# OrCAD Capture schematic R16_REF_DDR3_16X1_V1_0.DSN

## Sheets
1 05 DRAM DDR3 16bitx1: size A3; title: R16_REF_DDR3_16X1; rev: 0.1; note: DDR3 16X1
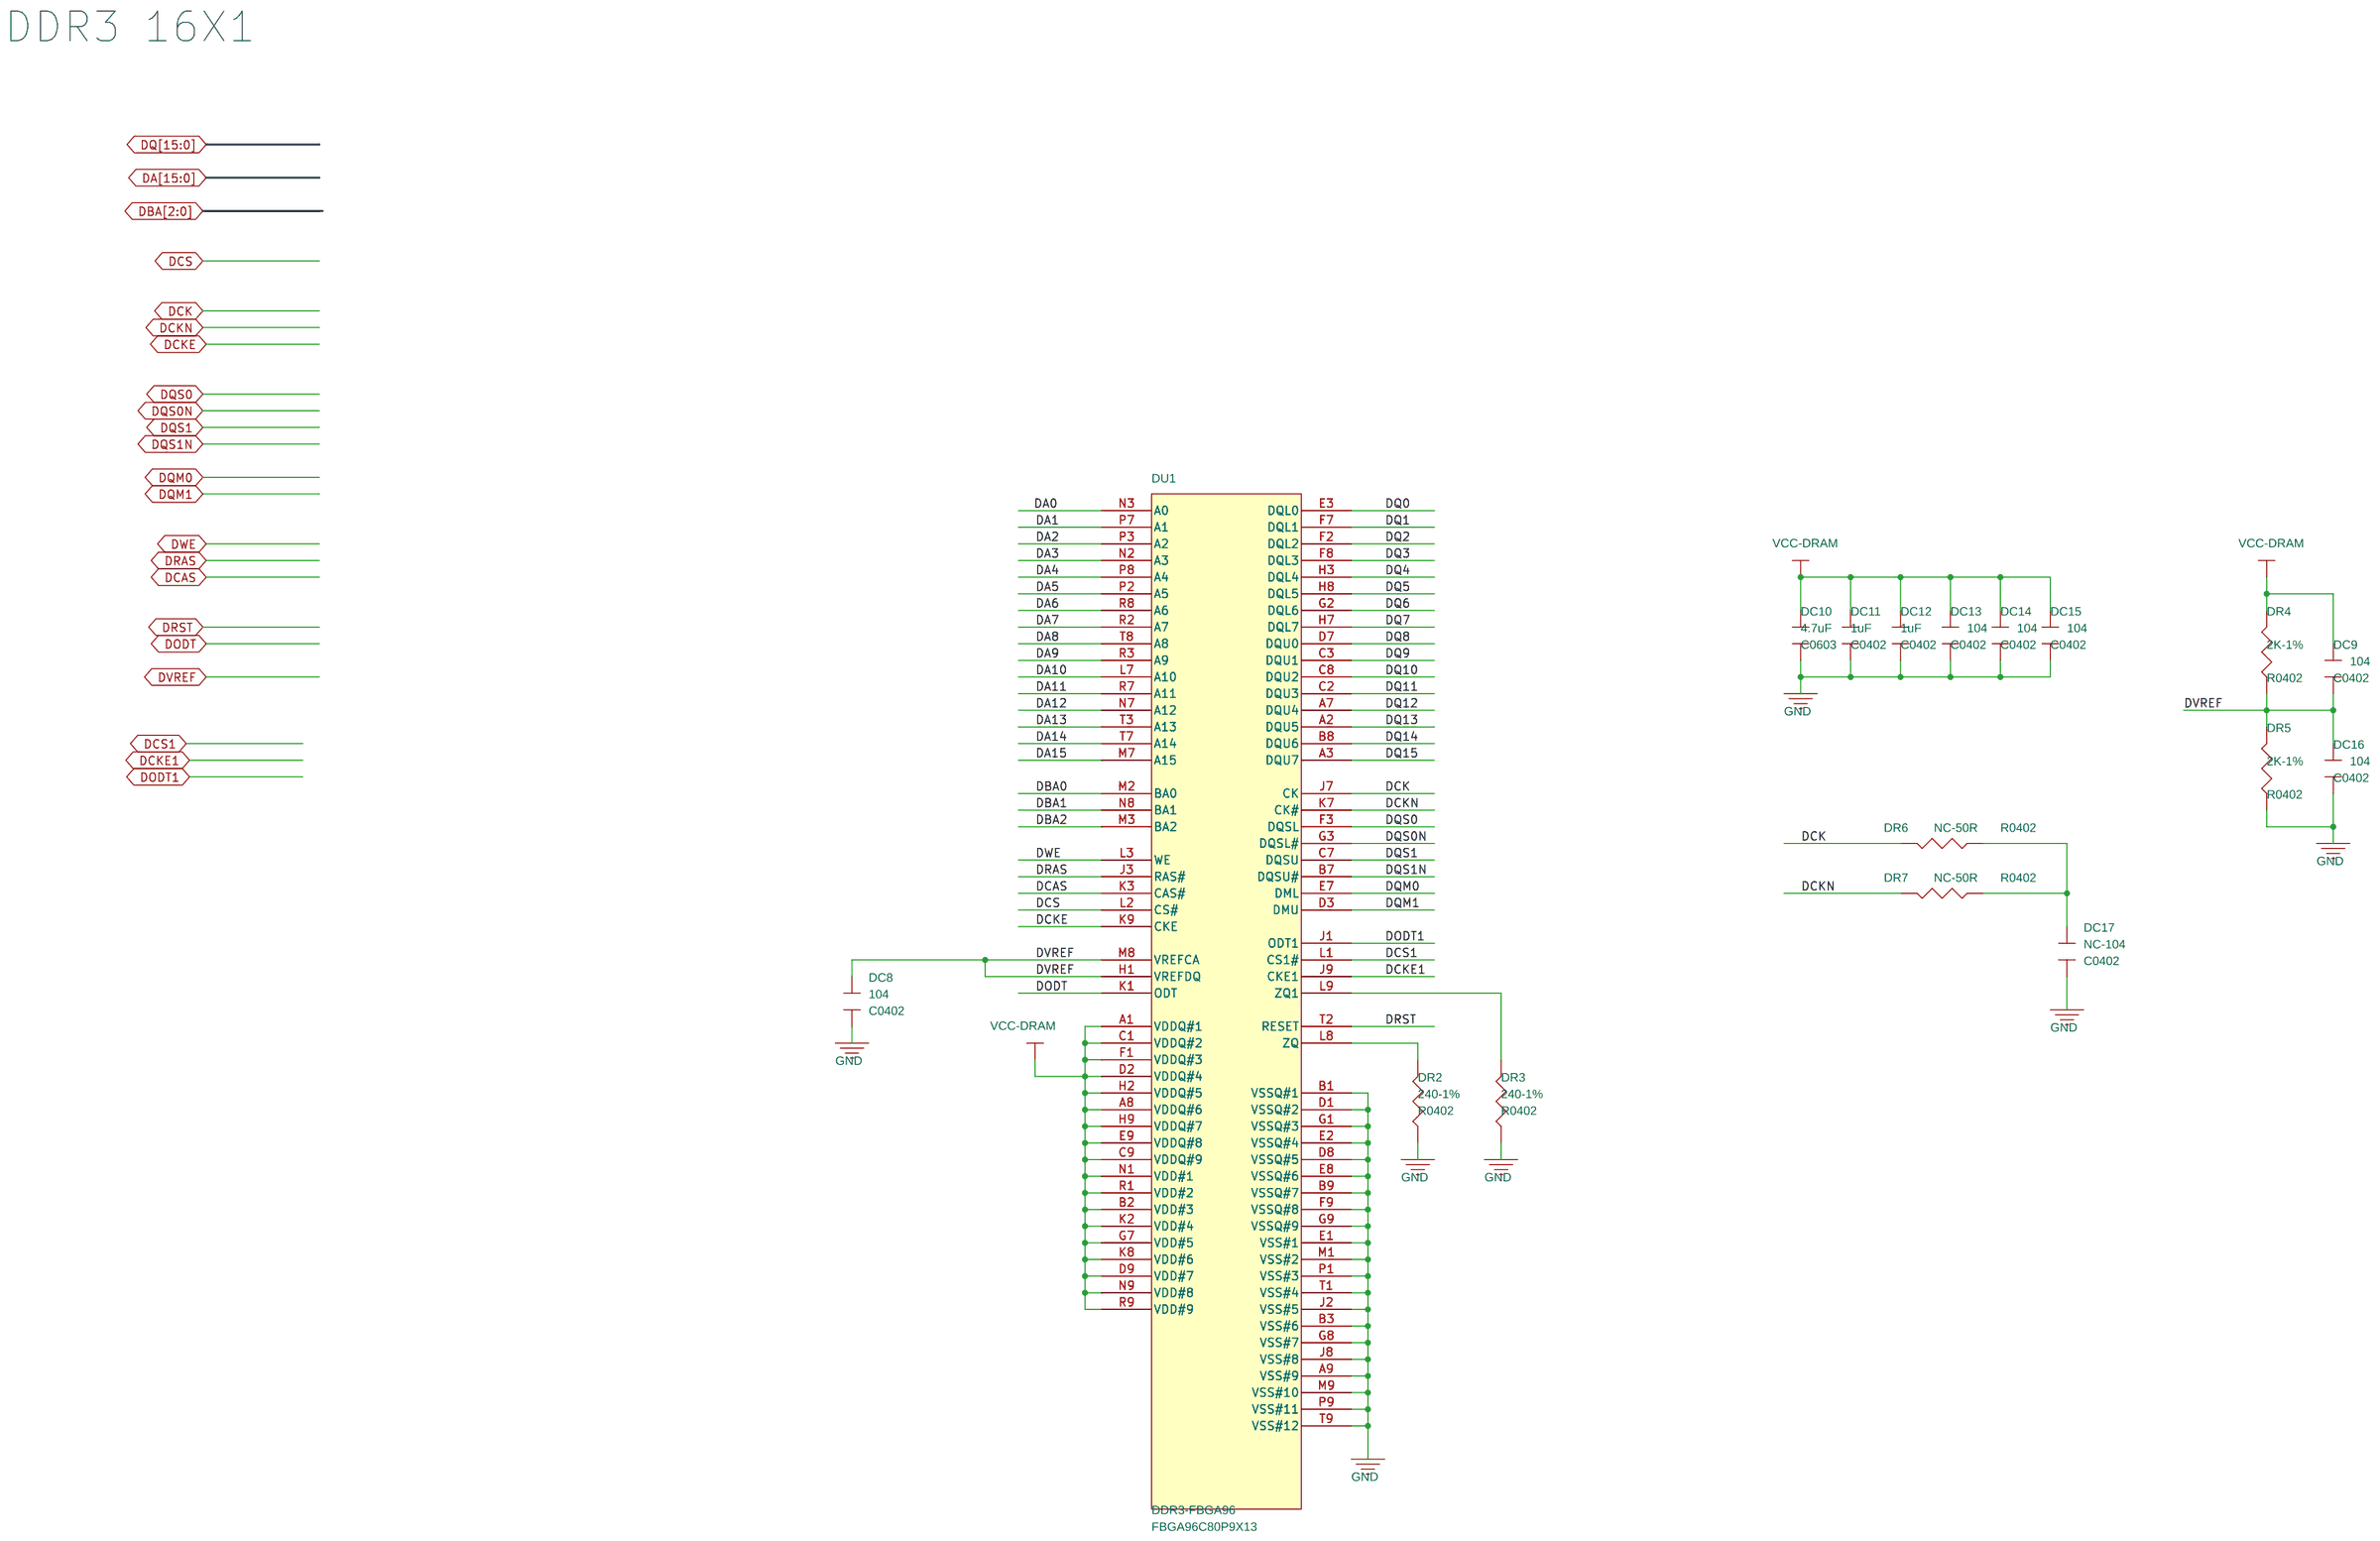
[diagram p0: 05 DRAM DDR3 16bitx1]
2 06 CPU: size A2; note: CPU
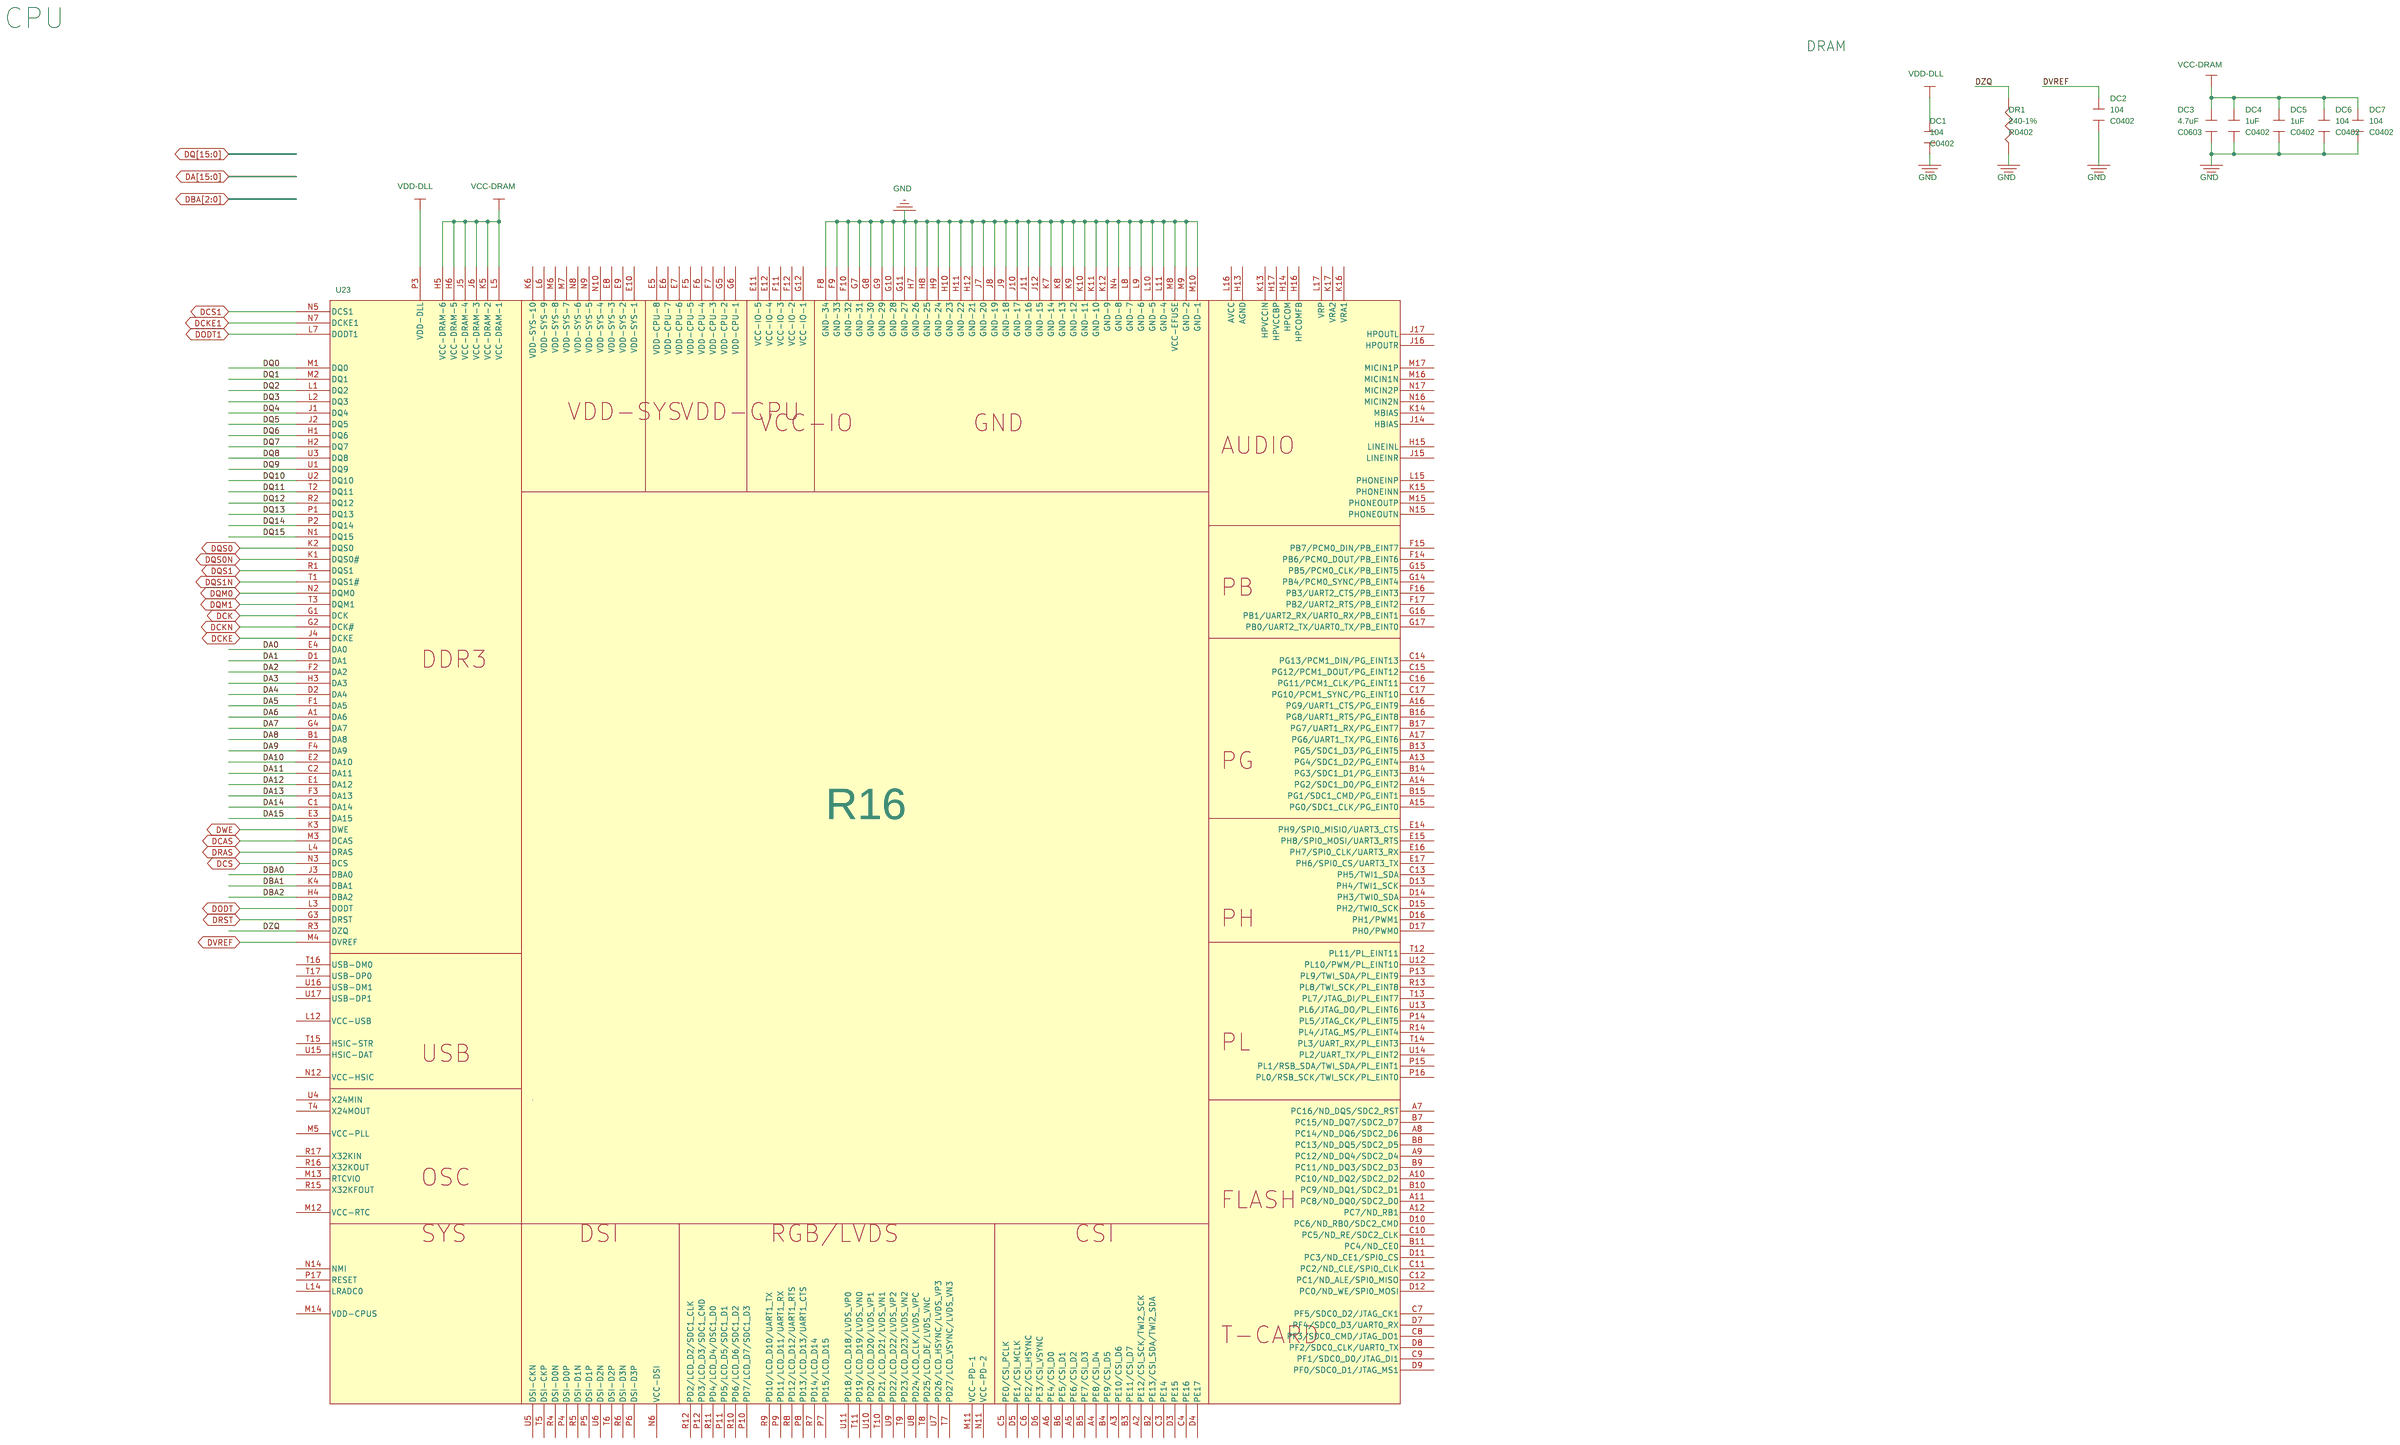
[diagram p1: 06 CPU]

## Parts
sheet 05 DRAM DDR3 16bitx1
DC8  104  [C0402]
DC9  104  [C0402]
DC10  4.7uF  [C0603]
DC11  1uF  [C0402]
DC12  1uF  [C0402]
DC13  104  [C0402]
DC14  104  [C0402]
DC15  104  [C0402]
DC16  104  [C0402]
DC17  NC-104  [C0402]
DR2  240-1%  [R0402]
DR3  240-1%  [R0402]
DR4  2K-1%  [R0402]
DR5  2K-1%  [R0402]
DR6  NC-50R  [R0402]
DR7  NC-50R  [R0402]
DU1  DDR3-FBGA96  [FBGA96C80P9X13]
sheet 06 CPU
DC1  104  [C0402]
DC2  104  [C0402]
DC3  4.7uF  [C0603]
DC4  1uF  [C0402]
DC5  1uF  [C0402]
DC6  104  [C0402]
DC7  104  [C0402]
DR1  240-1%  [R0402]
U23  R16  [BGA282P0_80B14X14H1_30]

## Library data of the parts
DC1-DC8 DC17 = CAPACITOR_0: PAGE: 2
DC9 DC16 = CAPACITOR_0: PAGE: 1; ROOM: RES_DVREF
DC10-DC12 = CAPACITOR_0: PAGE: 2; ROOM: CAP
DC13-DC15 = CAP_0: ROOM: CAP
DR1-DR3 DR6 DR7 = R
DR4 DR5 = ?_0: ROOM: RES_DVREF
DU1 = DDR3_1
U23 = bga280_4

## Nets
GND: DC1.1 DC2.1 DC3.1 DC4.1 DC5.1 DC6.1 DC7.1 DC8.1 DC10.1 DC11.1 DC12.1 DC13.2 DC14.2 DC15.2 DC16.1 DC17.1 DR1.1 DR2.1 DR3.1 DR5.1 DU1.A9(VSS#9) DU1.B1(VSSQ#1) DU1.B3(VSS#6) DU1.B9(VSSQ#7) DU1.D1(VSSQ#2) DU1.D8(VSSQ#5) DU1.E1(VSS#1) DU1.E2(VSSQ#4) DU1.E8(VSSQ#6) DU1.F9(VSSQ#8) DU1.G1(VSSQ#3) DU1.G8(VSS#7) DU1.G9(VSSQ#9) DU1.J2(VSS#5) DU1.J8(VSS#8) DU1.M1(VSS#2) DU1.M9(VSS#10) DU1.P1(VSS#3) DU1.P9(VSS#11) DU1.T1(VSS#4) DU1.T9(VSS#12) U23.F8(GND-34) U23.F9(GND-33) U23.F10(GND-32) U23.G7(GND-31) U23.G8(GND-30) U23.G9(GND-29) U23.G10(GND-28) U23.G11(GND-27) U23.H7(GND-26) U23.H8(GND-25) U23.H9(GND-24) U23.H10(GND-23) U23.H11(GND-22) U23.H12(GND-21) U23.J7(GND-20) U23.J8(GND-19) U23.J9(GND-18) U23.J10(GND-17) U23.J11(GND-16) U23.J12(GND-15) U23.K7(GND-14) U23.K8(GND-13) U23.K9(GND-12) U23.K10(GND-11) U23.K11(GND-10) U23.K12(GND-9) U23.L8(GND-7) U23.L9(GND-6) U23.L10(GND-5) U23.L11(GND-4) U23.M8(VCC-EFUSE) U23.M9(GND-2) U23.M10(GND-1) U23.N4(GND-8)
VCC-DRAM: DC3.2 DC4.2 DC5.2 DC6.2 DC7.2 DC9.2 DC10.2 DC11.2 DC12.2 DC13.1 DC14.1 DC15.1 DR4.2 DU1.A1(VDDQ#1) DU1.A8(VDDQ#6) DU1.B2(VDD#3) DU1.C1(VDDQ#2) DU1.C9(VDDQ#9) DU1.D2(VDDQ#4) DU1.D9(VDD#7) DU1.E9(VDDQ#8) DU1.F1(VDDQ#3) DU1.G7(VDD#5) DU1.H2(VDDQ#5) DU1.H9(VDDQ#7) DU1.K2(VDD#4) DU1.K8(VDD#6) DU1.N1(VDD#1) DU1.N9(VDD#8) DU1.R1(VDD#2) DU1.R9(VDD#9) U23.H5(VCC-DRAM-6) U23.H6(VCC-DRAM-5) U23.J5(VCC-DRAM-4) U23.J6(VCC-DRAM-3) U23.K5(VCC-DRAM-2) U23.L5(VCC-DRAM-1)
VDD-DLL: DC1.2 U23.P3(VDD-DLL)
DA0: DU1.N3(A0) U23.E4(DA0)
DA1: DU1.P7(A1) U23.D1(DA1)
DA2: DU1.P3(A2) U23.F2(DA2)
DA3: DU1.N2(A3) U23.H3(DA3)
DA4: DU1.P8(A4) U23.D2(DA4)
DA5: DU1.P2(A5) U23.F1(DA5)
DA6: DU1.R8(A6) U23.A1(DA6)
DA7: DU1.R2(A7) U23.G4(DA7)
DA8: DU1.T8(A8) U23.B1(DA8)
DA9: DU1.R3(A9) U23.F4(DA9)
DA10: DU1.L7(A10) U23.E2(DA10)
DA11: DU1.R7(A11) U23.C2(DA11)
DA12: DU1.N7(A12) U23.E1(DA12)
DA13: DU1.T3(A13) U23.F3(DA13)
DA14: DU1.T7(A14) U23.C1(DA14)
DA15: DU1.M7(A15) U23.E3(DA15)
DBA0: DU1.M2(BA0) U23.J3(DBA0)
DBA1: DU1.N8(BA1) U23.K4(DBA1)
DBA2: DU1.M3(BA2) U23.H4(DBA2)
DCAS: DU1.K3(CAS#) U23.M3(DCAS)
DCK: DR6.2 DU1.J7(CK) U23.G1(DCK)
DCKE: DU1.K9(CKE) U23.J4(DCKE)
DCKE1: DU1.J9(CKE1) U23.N7(DCKE1)
DCKN: DR7.2 DU1.K7(CK#) U23.G2(DCK#)
DCS: DU1.L2(CS#) U23.N3(DCS)
DCS1: DU1.L1(CS1#) U23.N5(DCS1)
DODT: DU1.K1(ODT) U23.L3(DODT)
DODT1: DU1.J1(ODT1) U23.L7(DODT1)
DQ0: DU1.E3(DQL0) U23.M1(DQ0)
DQ1: DU1.F7(DQL1) U23.M2(DQ1)
DQ2: DU1.F2(DQL2) U23.L1(DQ2)
DQ3: DU1.F8(DQL3) U23.L2(DQ3)
DQ4: DU1.H3(DQL4) U23.J1(DQ4)
DQ5: DU1.H8(DQL5) U23.J2(DQ5)
DQ6: DU1.G2(DQL6) U23.H1(DQ6)
DQ7: DU1.H7(DQL7) U23.H2(DQ7)
DQ8: DU1.D7(DQU0) U23.U3(DQ8)
DQ9: DU1.C3(DQU1) U23.U1(DQ9)
DQ10: DU1.C8(DQU2) U23.U2(DQ10)
DQ11: DU1.C2(DQU3) U23.T2(DQ11)
DQ12: DU1.A7(DQU4) U23.R2(DQ12)
DQ13: DU1.A2(DQU5) U23.P1(DQ13)
DQ14: DU1.B8(DQU6) U23.P2(DQ14)
DQ15: DU1.A3(DQU7) U23.N1(DQ15)
DQM0: DU1.E7(DML) U23.N2(DQM0)
DQM1: DU1.D3(DMU) U23.T3(DQM1)
DQS0: DU1.F3(DQSL) U23.K2(DQS0)
DQS0N: DU1.G3(DQSL#) U23.K1(DQS0#)
DQS1: DU1.C7(DQSU) U23.R1(DQS1)
DQS1N: DU1.B7(DQSU#) U23.T1(DQS1#)
DRAS: DU1.J3(RAS#) U23.L4(DRAS)
DRST: DU1.T2(RESET) U23.G3(DRST)
DVREF: DC2.2 DC8.2 DC9.1 DC16.2 DR4.1 DR5.2 DU1.H1(VREFDQ) DU1.M8(VREFCA) U23.M4(DVREF)
DWE: DU1.L3(WE) U23.K3(DWE)
DZQ: DR1.2 U23.R3(DZQ)
N17523254: DR2.2 DU1.L8(ZQ)
N18069975: DR3.2 DU1.L9(ZQ1)
N18151313: DC17.2 DR6.1 DR7.1

Not connected (* = marked no-connect by the designer): U23 A2(PE12/CSI_SCK/TWI2_SCK) A3(PE10/CSI_D6) A4(PE8/CSI_D4) A5(PE6/CSI_D2) A6(PE4/CSI_D0) A7(PC16/ND_DQS/SDC2_RST) A8(PC14/ND_DQ6/SDC2_D6) A9(PC12/ND_DQ4/SDC2_D4) A10(PC10/ND_DQ2/SDC2_D2) A11(PC8/ND_DQ0/SDC2_D0) A12(PC7/ND_RB1) A13(PG4/SDC1_D2/PG_EINT4) A14(PG2/SDC1_D0/PG_EINT2) A15(PG0/SDC1_CLK/PG_EINT0) A16(PG9/UART1_CTS/PG_EINT9) A17(PG6/UART1_TX/PG_EINT6) B2(PE13/CSI_SDA/TWI2_SDA) B3(PE11/CSI_D7) B4(PE9/CSI_D5) B5(PE7/CSI_D3) B6(PE5/CSI_D1) B7(PC15/ND_DQ7/SDC2_D7) B8(PC13/ND_DQ5/SDC2_D5) B9(PC11/ND_DQ3/SDC2_D3) B10(PC9/ND_DQ1/SDC2_D1) B11(PC4/ND_CE0) B13(PG5/SDC1_D3/PG_EINT5) B14(PG3/SDC1_D1/PG_EINT3) B15(PG1/SDC1_CMD/PG_EINT1) B16(PG8/UART1_RTS/PG_EINT8) B17(PG7/UART1_RX/PG_EINT7) C3(PE14) C4(PE16) C5(PE0/CSI_PCLK) C6(PE2/CSI_HSYNC) C7(PF5/SDC0_D2/JTAG_CK1) C8(PF3/SDC0_CMD/JTAG_DO1) C9(PF1/SDC0_D0/JTAG_DI1) C10(PC5/ND_RE/SDC2_CLK) C11(PC2/ND_CLE/SPI0_CLK) C12(PC1/ND_ALE/SPI0_MISO) C13(PH5/TWI1_SDA) C14(PG13/PCM1_DIN/PG_EINT13) C15(PG12/PCM1_DOUT/PG_EINT12) C16(PG11/PCM1_CLK/PG_EINT11) C17(PG10/PCM1_SYNC/PG_EINT10) D3(PE15) D4(PE17) D5(PE1/CSI_MCLK) D6(PE3/CSI_VSYNC) D7(PF4/SDC0_D3/UART0_RX) D8(PF2/SDC0_CLK/UART0_TX) D9(PF0/SDC0_D1/JTAG_MS1) D10(PC6/ND_RB0/SDC2_CMD) D11(PC3/ND_CE1/SPI0_CS) D12(PC0/ND_WE/SPI0_MOSI) D13(PH4/TWI1_SCK) D14(PH3/TWI0_SDA) D15(PH2/TWI0_SCK) D16(PH1/PWM1) D17(PH0/PWM0) E5(VDD-CPU-8) E6(VDD-CPU-7) E7(VDD-CPU-6) E8(VDD-SYS-3) E9(VDD-SYS-2) E10(VDD-SYS-1) E11(VCC-IO-5) E12(VCC-IO-4) E14(PH9/SPI0_MISIO/UART3_CTS) E15(PH8/SPI0_MOSI/UART3_RTS) E16(PH7/SPI0_CLK/UART3_RX) E17(PH6/SPI0_CS/UART3_TX) F5(VDD-CPU-5) F6(VDD-CPU-4) F7(VDD-CPU-3) F11(VCC-IO-3) F12(VCC-IO-2) F14(PB6/PCM0_DOUT/PB_EINT6) F15(PB7/PCM0_DIN/PB_EINT7) F16(PB3/UART2_CTS/PB_EINT3) F17(PB2/UART2_RTS/PB_EINT2) G5(VDD-CPU-2) G6(VDD-CPU-1) G12(VCC-IO-1) G14(PB4/PCM0_SYNC/PB_EINT4) G15(PB5/PCM0_CLK/PB_EINT5) G16(PB1/UART2_RX/UART0_RX/PB_EINT1) G17(PB0/UART2_TX/UART0_TX/PB_EINT0) H13(AGND) H14(HPCOM) H15(LINEINL) H16(HPCOMFB) H17(HPVCCBP) J14(HBIAS) J15(LINEINR) J16(HPOUTR) J17(HPOUTL) K6(VDD-SYS-10) K13(HPVCCIN) K14(MBIAS) K15(PHONEINN) K16(VRA1) K17(VRA2) L6(VDD-SYS-9) L12(VCC-USB) L14(LRADC0) L15(PHONEINP) L16(AVCC) L17(VRP) M5(VCC-PLL) M6(VDD-SYS-8) M7(VDD-SYS-7) M11(VCC-PD-1) M12(VCC-RTC) M13(RTCVIO) M14(VDD-CPUS) M15(PHONEOUTP) M16(MICIN1N) M17(MICIN1P) N6(VCC-DSI) N8(VDD-SYS-6) N9(VDD-SYS-5) N10(VDD-SYS-4) N11(VCC-PD-2) N12(VCC-HSIC) N14(NMI) N15(PHONEOUTN) N16(MICIN2N) N17(MICIN2P) P4(DSI-D0P) P5(DSI-D1P) P6(DSI-D3P) P7(PD15/LCD_D15) P8(PD13/LCD_D13/UART1_CTS) P9(PD11/LCD_D11/UART1_RX) P10(PD7/LCD_D7/SDC1_D3) P11(PD5/LCD_D5/SDC1_D1) P12(PD3/LCD_D3/SDC1_CMD) P13(PL9/TWI_SDA/PL_EINT9) P14(PL5/JTAG_CK/PL_EINT5) P15(PL1/RSB_SDA/TWI_SDA/PL_EINT1) P16(PL0/RSB_SCK/TWI_SCK/PL_EINT0) P17(RESET) R4(DSI-D0N) R5(DSI-D1N) R6(DSI-D3N) R7(PD14/LCD_D14) R8(PD12/LCD_D12/UART1_RTS) R9(PD10/LCD_D10/UART1_TX) R10(PD6/LCD_D6/SDC1_D2) R11(PD4/LCD_D4/DSC1_D0) R12(PD2/LCD_D2/SDC1_CLK) R13(PL8/TWI_SCK/PL_EINT8) R14(PL4/JTAG_MS/PL_EINT4) R15(X32KFOUT) R16(X32KOUT) R17(X32KIN) T4(X24MOUT) T5(DSI-CKP) T6(DSI-D2P) T7(PD27/LCD_VSYNC/LVDS_VN3) T8(PD25/LCD_DE/LVDS_VNC) T9(PD23/LCD_D23/LVDS_VN2) T10(PD21/LCD_D21/LVDS_VN1) T11(PD19/LCD_D19/LVDS_VN0) T12(PL11/PL_EINT11) T13(PL7/JTAG_DI/PL_EINT7) T14(PL3/UART_RX/PL_EINT3) T15(HSIC-STR) T16(USB-DM0) T17(USB-DP0) U4(X24MIN) U5(DSI-CKN) U6(DSI-D2N) U7(PD26/LCD_HSYNC/LVDS_VP3) U8(PD24/LCD_CLK/LVDS_VPC) U9(PD22/LCD_D22/LVDS_VP2) U10(PD20/LCD_D20/LVDS_VP1) U11(PD18/LCD_D18/LVDS_VP0) U12(PL10/PWM/PL_EINT10) U13(PL6/JTAG_DO/PL_EINT6) U14(PL2/UART_TX/PL_EINT2) U15(HSIC-DAT) U16(USB-DM1) U17(USB-DP1)

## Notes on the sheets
sheet 1
- DDR3 16X1
sheet 2
- CPU
- DRAM
